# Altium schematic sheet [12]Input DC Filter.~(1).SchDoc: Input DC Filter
size A4; Organization: BQR; Address1: Reliability Engineering; Address2: Optimized Maintenance; Address3: www.bqr.com; Address4: www.bqr-digital.com; DocumentNumber: DOC13; SheetNumber: 8; SheetTotal: 13
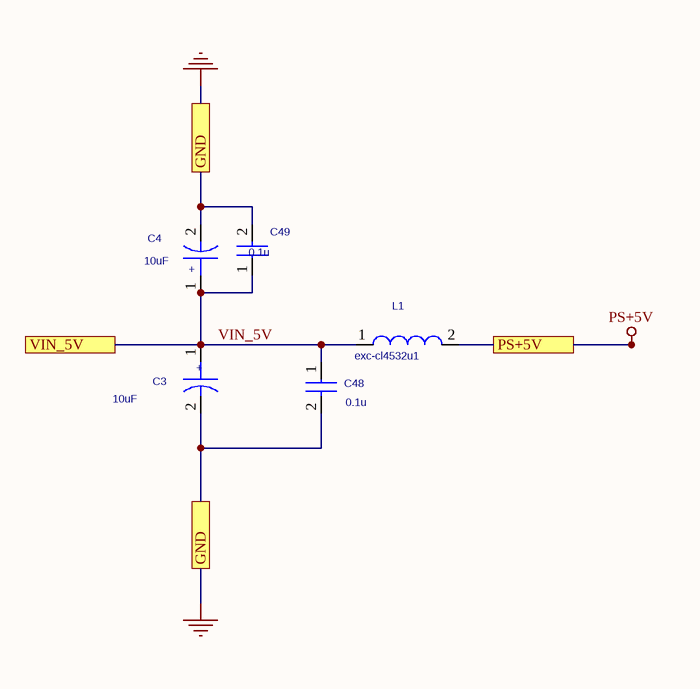
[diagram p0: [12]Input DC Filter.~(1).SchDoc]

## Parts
C3  10uF  [cap_c-case]
C4  10uF  [cap_c-case]
C48  0.1u  [0603]
C49  0.1u  [0603]
L1  exc-cl4532u1  [exc-cl4532u1]

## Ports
GND, PS+5V, VIN_5V

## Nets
GND: C3.2 C4.2 C48.2 C49.2 ; port GND
PS+5V: L1.2 ; port PS+5V
VIN_5V: C3.1 C4.1 C48.1 C49.1 L1.1 ; port VIN_5V

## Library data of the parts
C3 = Cap_Polar_1: CAP TANT 10UF 6.3V 10% 1206; Manufacturer: AVX_1; Manufacturer P/N: TAJA106K006R; fiX_Manuf: Murata; Catalog Number: CAP00039; fiX_Func: DC Filter (12); SDTA_V(Voltage): 5
C4 = Cap_Polar_1: CAP TANT 10UF 20V 10% 2312; Manufacturer P/N: TAJC106K020R; Manufacturer: AVX; fiX_Manuf: Murata; Catalog Number: CAP00001; SDTA_I(Isurge): 0.0001; SDTA_Par5(Vrev): 0.001; SDTA_V(Voltage): 5; fiX_Func: DC Filter (12)
C48 = Capacitor_3: CAP CER 0.1UF 16V X7R 0603; Manufacturer: Murata; Manufacturer P/N: GRM188R71C104KA01D; Catalog Number: CAP00036; fiX_Func: DC Filter (12); SDTA_V(Voltage): 5
C49 = Capacitor_3: CAP CER 0.1UF 16V X7R 0603; Manufacturer: Murata; Manufacturer P/N: GRM188R71C104KA01D; Catalog Number: CAP00036; SDTA_V(Voltage): 5; fiX_Func: DC Filter (12)
L1 = Inductor: FERRITE BEAD 115 OHM 1812 1LN; Manufacturer: Panasonic; fiX_Manuf: JST; Catalog Number: IND00022; fiX_Func: DC Filter (12); SDTA_I(Ioper): 0.07; SDTA_P(Power): 0.15; SDTA_V(Vdiel): 5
